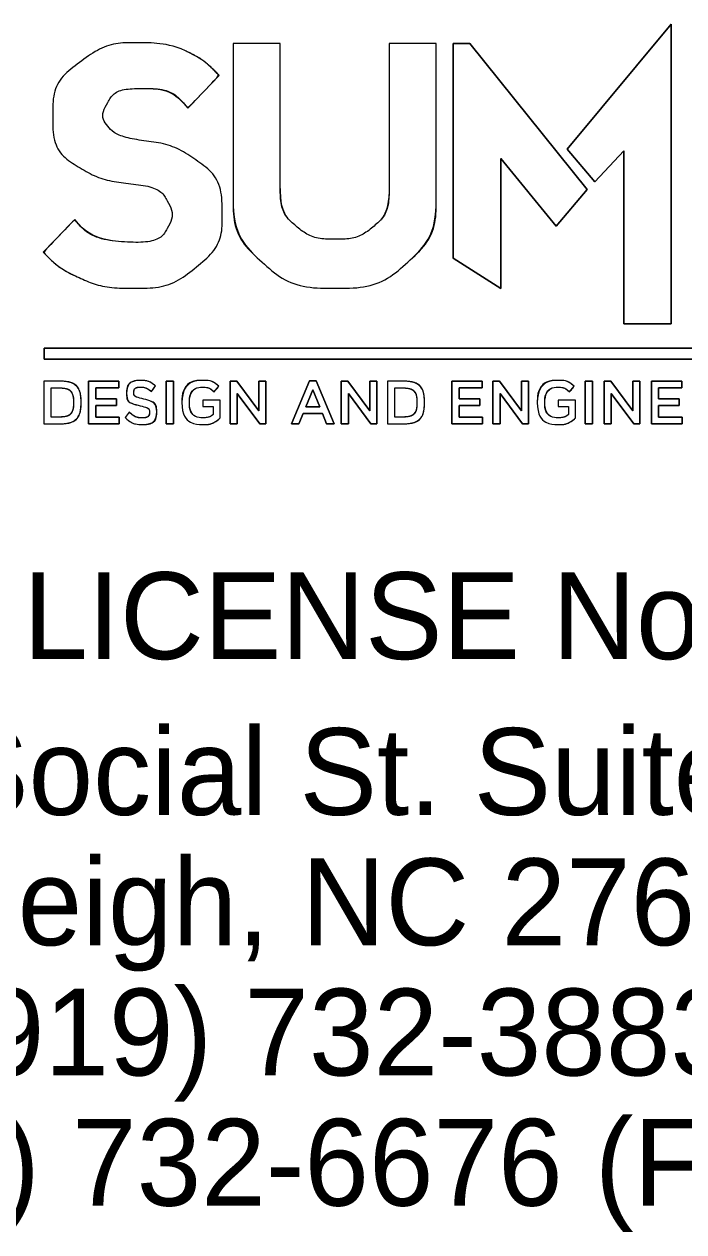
# Model space of a CAD drawing. Extents: x -0.67 to 3.05, y 0 to 1.8.
# Drawn here: x 2.6579 to 2.7165, y 1.2524 to 1.3595 of the extents above; entities that cross this region are included whole.
import ezdxf

# ---------------------------------------------------------------- set-up
doc = ezdxf.new("R2010")
doc.units = 0
doc.layers.add('Sheet Plan CELL', color=7, linetype='Continuous')

msp = doc.modelspace()

# ---------------------------------------------------------------- linework, layer by layer
at = {"layer": 'Sheet Plan CELL'}
for p, q in [((2.67246, 1.35204), (2.67524, 1.35495)), ((2.66243, 1.34217), (2.65964, 1.33926)), ((2.66925, 1.32691), (2.66959, 1.32741)), ((2.6748, 1.32688), (2.67521, 1.32738)), ((2.70633, 1.32688), (2.70674, 1.32738)), ((2.66703, 1.32679), (2.66703, 1.32678)), ((2.66767, 1.32684), (2.66767, 1.32685)), ((2.66232, 1.32594), (2.66232, 1.32593)), ((2.66299, 1.32594), (2.66299, 1.32595)), ((2.66727, 1.32507), (2.66689, 1.3246)), ((2.66906, 1.32507), (2.66906, 1.32506)), ((2.6697, 1.32512), (2.6697, 1.32513)), ((2.67194, 1.32594), (2.67194, 1.32593)), ((2.67261, 1.32594), (2.67261, 1.32595)), ((2.69279, 1.32594), (2.69279, 1.32593)), ((2.69346, 1.32594), (2.69346, 1.32595)), ((2.70347, 1.32594), (2.70347, 1.32593)), ((2.70414, 1.32594), (2.70414, 1.32595))]:
    msp.add_line(p, q, dxfattribs=at)
for points in [[(2.71534, 1.3595), (2.71534, 1.33291), (2.71115, 1.33291), (2.71115, 1.34825), (2.70856, 1.3455), (2.70612, 1.34841), (2.71534, 1.3595)], [(2.70612, 1.34841), (2.70856, 1.3455), (2.71115, 1.34825), (2.71115, 1.33291), (2.71534, 1.33291), (2.71534, 1.3595), (2.70612, 1.34841)], [(2.68066, 1.34522), (2.68066, 1.35777), (2.67647, 1.35777), (2.67647, 1.34406)], [(2.69451, 1.34406), (2.69451, 1.35777), (2.69032, 1.35777), (2.69032, 1.34522)], [(2.69749, 1.35777), (2.70788, 1.34484), (2.70514, 1.34158), (2.70023, 1.34757), (2.70023, 1.33606), (2.69601, 1.33874), (2.69601, 1.35777), (2.69749, 1.35777)], [(2.69601, 1.35777), (2.69601, 1.33874), (2.70023, 1.33606), (2.70023, 1.34757), (2.70514, 1.34158), (2.70788, 1.34484), (2.69749, 1.35777), (2.69601, 1.35777)], [(2.76119, 1.32977), (2.65972, 1.32977), (2.65972, 1.33077), (2.76119, 1.33077), (2.76119, 1.32977)], [(2.76119, 1.33077), (2.65972, 1.33077), (2.65972, 1.32977), (2.76119, 1.32977), (2.76119, 1.33077)], [(2.66106, 1.32783), (2.6597, 1.32783), (2.6597, 1.32405), (2.66106, 1.32405)], [(2.66106, 1.32465), (2.66034, 1.32465), (2.66034, 1.32723), (2.66106, 1.32723)], [(2.66365, 1.32783), (2.66635, 1.32783), (2.66635, 1.32724), (2.66429, 1.32724), (2.66429, 1.32625), (2.66612, 1.32625), (2.66612, 1.32566), (2.66429, 1.32566), (2.66429, 1.32464), (2.66637, 1.32464), (2.66637, 1.32405), (2.66365, 1.32405), (2.66365, 1.32783)], [(2.66365, 1.32405), (2.66637, 1.32405), (2.66637, 1.32464), (2.66429, 1.32464), (2.66429, 1.32566), (2.66612, 1.32566), (2.66612, 1.32625), (2.66429, 1.32625), (2.66429, 1.32724), (2.66635, 1.32724), (2.66635, 1.32783), (2.66365, 1.32783), (2.66365, 1.32405)], [(2.67054, 1.32783), (2.67118, 1.32783), (2.67118, 1.32405), (2.67054, 1.32405), (2.67054, 1.32783)], [(2.67054, 1.32405), (2.67118, 1.32405), (2.67118, 1.32783), (2.67054, 1.32783), (2.67054, 1.32405)], [(2.67622, 1.32783), (2.67681, 1.32783), (2.67876, 1.32521), (2.67876, 1.32783), (2.67938, 1.32783), (2.67938, 1.32405), (2.67885, 1.32405), (2.67685, 1.32674), (2.67685, 1.32405), (2.67622, 1.32405), (2.67622, 1.32783)], [(2.67622, 1.32405), (2.67685, 1.32405), (2.67685, 1.32674), (2.67885, 1.32405), (2.67938, 1.32405), (2.67938, 1.32783), (2.67876, 1.32783), (2.67876, 1.32521), (2.67681, 1.32783), (2.67622, 1.32783), (2.67622, 1.32405)], [(2.68326, 1.32786), (2.68386, 1.32786), (2.68546, 1.32405), (2.68478, 1.32405), (2.68441, 1.32496), (2.68269, 1.32496), (2.68232, 1.32405), (2.68167, 1.32405), (2.68326, 1.32786)], [(2.68167, 1.32405), (2.68232, 1.32405), (2.68269, 1.32496), (2.68441, 1.32496), (2.68478, 1.32405), (2.68546, 1.32405), (2.68386, 1.32786), (2.68326, 1.32786), (2.68167, 1.32405)], [(2.68608, 1.32783), (2.68667, 1.32783), (2.68861, 1.32521), (2.68861, 1.32783), (2.68924, 1.32783), (2.68924, 1.32405), (2.68871, 1.32405), (2.68671, 1.32674), (2.68671, 1.32405), (2.68608, 1.32405), (2.68608, 1.32783)], [(2.68608, 1.32405), (2.68671, 1.32405), (2.68671, 1.32674), (2.68871, 1.32405), (2.68924, 1.32405), (2.68924, 1.32783), (2.68861, 1.32783), (2.68861, 1.32521), (2.68667, 1.32783), (2.68608, 1.32783), (2.68608, 1.32405)], [(2.69153, 1.32783), (2.69018, 1.32783), (2.69018, 1.32405), (2.69153, 1.32405)], [(2.69153, 1.32465), (2.69082, 1.32465), (2.69082, 1.32723), (2.69153, 1.32723)], [(2.6959, 1.32783), (2.69859, 1.32783), (2.69859, 1.32724), (2.69653, 1.32724), (2.69653, 1.32625), (2.69836, 1.32625), (2.69836, 1.32566), (2.69653, 1.32566), (2.69653, 1.32464), (2.69861, 1.32464), (2.69861, 1.32405), (2.6959, 1.32405), (2.6959, 1.32783)], [(2.6959, 1.32405), (2.69861, 1.32405), (2.69861, 1.32464), (2.69653, 1.32464), (2.69653, 1.32566), (2.69836, 1.32566), (2.69836, 1.32625), (2.69653, 1.32625), (2.69653, 1.32724), (2.69859, 1.32724), (2.69859, 1.32783), (2.6959, 1.32783), (2.6959, 1.32405)], [(2.69953, 1.32783), (2.70012, 1.32783), (2.70207, 1.32521), (2.70207, 1.32783), (2.70269, 1.32783), (2.70269, 1.32405), (2.70216, 1.32405), (2.70016, 1.32674), (2.70016, 1.32405), (2.69953, 1.32405), (2.69953, 1.32783)], [(2.69953, 1.32405), (2.70016, 1.32405), (2.70016, 1.32674), (2.70216, 1.32405), (2.70269, 1.32405), (2.70269, 1.32783), (2.70207, 1.32783), (2.70207, 1.32521), (2.70012, 1.32783), (2.69953, 1.32783), (2.69953, 1.32405)], [(2.70773, 1.32783), (2.70837, 1.32783), (2.70837, 1.32405), (2.70773, 1.32405), (2.70773, 1.32783)], [(2.70773, 1.32405), (2.70837, 1.32405), (2.70837, 1.32783), (2.70773, 1.32783), (2.70773, 1.32405)], [(2.70939, 1.32783), (2.70998, 1.32783), (2.71193, 1.32521), (2.71193, 1.32783), (2.71256, 1.32783), (2.71256, 1.32405), (2.71202, 1.32405), (2.71002, 1.32674), (2.71002, 1.32405), (2.70939, 1.32405), (2.70939, 1.32783)], [(2.70939, 1.32405), (2.71002, 1.32405), (2.71002, 1.32674), (2.71202, 1.32405), (2.71256, 1.32405), (2.71256, 1.32783), (2.71193, 1.32783), (2.71193, 1.32521), (2.70998, 1.32783), (2.70939, 1.32783), (2.70939, 1.32405)], [(2.7136, 1.32783), (2.71629, 1.32783), (2.71629, 1.32724), (2.71423, 1.32724), (2.71423, 1.32625), (2.71606, 1.32625), (2.71606, 1.32566), (2.71423, 1.32566), (2.71423, 1.32464), (2.71632, 1.32464), (2.71632, 1.32405), (2.7136, 1.32405), (2.7136, 1.32783)], [(2.7136, 1.32405), (2.71632, 1.32405), (2.71632, 1.32464), (2.71423, 1.32464), (2.71423, 1.32566), (2.71606, 1.32566), (2.71606, 1.32625), (2.71423, 1.32625), (2.71423, 1.32724), (2.71629, 1.32724), (2.71629, 1.32783), (2.7136, 1.32783), (2.7136, 1.32405)], [(2.67534, 1.32457), (2.67534, 1.32616), (2.67379, 1.32616), (2.67379, 1.32558), (2.67472, 1.32558), (2.67472, 1.32487)], [(2.68418, 1.32555), (2.68355, 1.32706), (2.68293, 1.32555), (2.68418, 1.32555)], [(2.68293, 1.32555), (2.68355, 1.32706), (2.68418, 1.32555), (2.68293, 1.32555)], [(2.70687, 1.32457), (2.70687, 1.32616), (2.70532, 1.32616), (2.70532, 1.32558), (2.70625, 1.32558), (2.70625, 1.32487)]]:
    msp.add_lwpolyline(points, dxfattribs=at)
for points, degree in [([(2.67225, 1.35713), (2.67331, 1.35664), (2.67431, 1.35592), (2.67524, 1.35495), (2.67524, 1.35495), (2.67246, 1.35204), (2.67246, 1.35204), (2.67153, 1.35321), (2.67023, 1.35379), (2.66855, 1.35379), (2.66688, 1.35379), (2.66582, 1.35338), (2.66535, 1.35255), (2.66489, 1.35173), (2.66489, 1.35103), (2.66535, 1.35045), (2.66582, 1.34987), (2.66688, 1.34943), (2.66855, 1.34914), (2.67032, 1.34895), (2.67192, 1.34834), (2.67336, 1.34732), (2.6748, 1.34631), (2.67552, 1.34469), (2.67552, 1.34246), (2.67552, 1.34071), (2.67475, 1.33921), (2.67322, 1.33796), (2.67168, 1.3367), (2.66989, 1.33607), (2.66784, 1.33607), (2.6659, 1.33607), (2.66428, 1.33636), (2.66298, 1.33694), (2.66168, 1.33752), (2.66057, 1.33829), (2.65964, 1.33926), (2.65964, 1.33926), (2.66243, 1.34217), (2.66243, 1.34217), (2.66335, 1.34101), (2.66493, 1.34033), (2.66716, 1.34013), (2.66902, 1.34013), (2.67018, 1.34055), (2.67064, 1.34137), (2.6711, 1.34219), (2.6711, 1.34301), (2.67064, 1.34384), (2.67018, 1.34466), (2.66902, 1.34517), (2.66716, 1.34536), (2.66549, 1.34556), (2.66396, 1.34609), (2.66256, 1.34696), (2.66117, 1.34783), (2.66047, 1.34933), (2.66047, 1.35146), (2.66047, 1.35339), (2.66127, 1.35494), (2.66285, 1.3561), (2.66443, 1.35727), (2.66606, 1.35785), (2.66773, 1.35785), (2.66967, 1.35785), (2.67118, 1.35761), (2.67225, 1.35713)], 3), ([(2.67225, 1.35713), (2.67118, 1.35761), (2.66967, 1.35785), (2.66773, 1.35785), (2.66606, 1.35785), (2.66443, 1.35727), (2.66285, 1.3561), (2.66127, 1.35494), (2.66047, 1.35339), (2.66047, 1.35146), (2.66047, 1.34933), (2.66117, 1.34783), (2.66256, 1.34696), (2.66396, 1.34609), (2.66549, 1.34556), (2.66716, 1.34536), (2.66902, 1.34517), (2.67018, 1.34466), (2.67064, 1.34384), (2.6711, 1.34301), (2.6711, 1.34219), (2.67064, 1.34137), (2.67018, 1.34055), (2.66902, 1.34013), (2.66716, 1.34013), (2.66493, 1.34033), (2.66335, 1.34101), (2.66243, 1.34217)], 3), ([(2.68066, 1.35777), (2.68066, 1.35777), (2.68066, 1.34522), (2.68066, 1.34522), (2.68066, 1.34357), (2.68113, 1.34236), (2.68206, 1.34159), (2.68299, 1.34081), (2.68416, 1.34042), (2.68555, 1.34042), (2.68694, 1.34042), (2.68805, 1.34081), (2.68898, 1.34159), (2.68991, 1.34236), (2.69032, 1.34357), (2.69032, 1.34522), (2.69032, 1.34522), (2.69032, 1.35777), (2.69032, 1.35777), (2.69032, 1.35777), (2.69451, 1.35777), (2.69451, 1.35777), (2.69451, 1.35777), (2.69451, 1.34406), (2.69451, 1.34406), (2.69451, 1.34183), (2.6937, 1.33994), (2.69198, 1.33839), (2.69026, 1.33684), (2.68813, 1.33607), (2.68553, 1.33607), (2.68293, 1.33607), (2.68077, 1.33684), (2.67905, 1.33839), (2.67733, 1.33994), (2.67647, 1.34183), (2.67647, 1.34406), (2.67647, 1.34406), (2.67647, 1.35777), (2.67647, 1.35777), (2.67647, 1.35777), (2.68066, 1.35777), (2.68066, 1.35777)], 3), ([(2.67524, 1.35495), (2.67431, 1.35592), (2.67331, 1.35664), (2.67225, 1.35713)], 2), ([(2.65964, 1.33926), (2.66057, 1.33829), (2.66168, 1.33752), (2.66298, 1.33694), (2.66428, 1.33636), (2.6659, 1.33607), (2.66784, 1.33607), (2.66989, 1.33607), (2.67168, 1.3367), (2.67322, 1.33796), (2.67475, 1.33921), (2.67552, 1.34071), (2.67552, 1.34246), (2.67552, 1.34469), (2.6748, 1.34631), (2.67336, 1.34732), (2.67192, 1.34834), (2.67032, 1.34895), (2.66855, 1.34914), (2.66688, 1.34943), (2.66582, 1.34987), (2.66535, 1.35045), (2.66489, 1.35103), (2.66489, 1.35173), (2.66535, 1.35255), (2.66582, 1.35338), (2.66688, 1.35379), (2.66855, 1.35379), (2.67023, 1.35379), (2.67153, 1.35321), (2.67246, 1.35204)], 3), ([(2.69032, 1.34522), (2.69032, 1.34357), (2.68991, 1.34236), (2.68898, 1.34159), (2.68805, 1.34081), (2.68694, 1.34042), (2.68555, 1.34042), (2.68416, 1.34042), (2.68299, 1.34081), (2.68206, 1.34159), (2.68113, 1.34236), (2.68066, 1.34357), (2.68066, 1.34522)], 3), ([(2.67647, 1.34406), (2.67647, 1.34183), (2.67733, 1.33994), (2.67905, 1.33839), (2.68077, 1.33684), (2.68293, 1.33607), (2.68553, 1.33607), (2.68813, 1.33607), (2.69026, 1.33684), (2.69198, 1.33839), (2.6937, 1.33994), (2.69451, 1.34183), (2.69451, 1.34406)], 3), ([(2.6597, 1.32783), (2.6597, 1.32783), (2.66106, 1.32783), (2.66106, 1.32783), (2.6622, 1.32783), (2.66299, 1.32702), (2.66299, 1.32595), (2.66299, 1.32595), (2.66299, 1.32594), (2.66299, 1.32594), (2.66299, 1.32487), (2.6622, 1.32405), (2.66106, 1.32405), (2.66106, 1.32405), (2.6597, 1.32405), (2.6597, 1.32405), (2.6597, 1.32405), (2.6597, 1.32783), (2.6597, 1.32783)], 3), ([(2.66034, 1.32723), (2.66034, 1.32723), (2.66034, 1.32465), (2.66034, 1.32465), (2.66034, 1.32465), (2.66106, 1.32465), (2.66106, 1.32465), (2.66182, 1.32465), (2.66232, 1.32519), (2.66232, 1.32593), (2.66232, 1.32593), (2.66232, 1.32594), (2.66232, 1.32594), (2.66232, 1.32668), (2.66182, 1.32723), (2.66106, 1.32723), (2.66106, 1.32723), (2.66034, 1.32723), (2.66034, 1.32723)], 3), ([(2.66299, 1.32595), (2.66299, 1.32702), (2.6622, 1.32783), (2.66106, 1.32783)], 2), ([(2.66106, 1.32723), (2.66182, 1.32723), (2.66232, 1.32668), (2.66232, 1.32594)], 2), ([(2.66689, 1.3246), (2.66689, 1.3246), (2.66727, 1.32507), (2.66727, 1.32507), (2.66762, 1.32476), (2.66797, 1.32458), (2.66842, 1.32458), (2.66881, 1.32458), (2.66906, 1.32478), (2.66906, 1.32506), (2.66906, 1.32506), (2.66906, 1.32507), (2.66906, 1.32507), (2.66906, 1.32534), (2.66892, 1.32548), (2.66824, 1.32565), (2.66747, 1.32584), (2.66703, 1.32608), (2.66703, 1.32678), (2.66703, 1.32678), (2.66703, 1.32679), (2.66703, 1.32679), (2.66703, 1.32744), (2.66755, 1.32789), (2.66827, 1.32789), (2.6688, 1.32789), (2.66922, 1.32772), (2.66959, 1.32741), (2.66959, 1.32741), (2.66925, 1.32691), (2.66925, 1.32691), (2.66892, 1.32716), (2.6686, 1.3273), (2.66826, 1.3273), (2.66789, 1.3273), (2.66767, 1.3271), (2.66767, 1.32685), (2.66767, 1.32685), (2.66767, 1.32684), (2.66767, 1.32684), (2.66767, 1.32655), (2.66784, 1.32642), (2.66854, 1.32624), (2.66931, 1.32605), (2.6697, 1.32576), (2.6697, 1.32513), (2.6697, 1.32513), (2.6697, 1.32512), (2.6697, 1.32512), (2.6697, 1.32441), (2.66917, 1.32399), (2.6684, 1.32399), (2.66785, 1.32399), (2.66732, 1.32419), (2.66689, 1.3246)], 3), ([(2.66959, 1.32741), (2.66922, 1.32772), (2.6688, 1.32789), (2.66827, 1.32789), (2.66755, 1.32789), (2.66703, 1.32744), (2.66703, 1.32679)], 3), ([(2.66767, 1.32685), (2.66767, 1.3271), (2.66789, 1.3273), (2.66826, 1.3273), (2.6686, 1.3273), (2.66892, 1.32716), (2.66925, 1.32691)], 3), ([(2.67194, 1.32593), (2.67194, 1.32593), (2.67194, 1.32594), (2.67194, 1.32594), (2.67194, 1.327), (2.67271, 1.3279), (2.67381, 1.3279), (2.67444, 1.3279), (2.67483, 1.32771), (2.67521, 1.32738), (2.67521, 1.32738), (2.6748, 1.32688), (2.6748, 1.32688), (2.67452, 1.32713), (2.67425, 1.32729), (2.67378, 1.32729), (2.67311, 1.32729), (2.67261, 1.32668), (2.67261, 1.32595), (2.67261, 1.32595), (2.67261, 1.32594), (2.67261, 1.32594), (2.67261, 1.32516), (2.6731, 1.32459), (2.67384, 1.32459), (2.67418, 1.32459), (2.6745, 1.3247), (2.67472, 1.32487), (2.67472, 1.32487), (2.67472, 1.32558), (2.67472, 1.32558), (2.67472, 1.32558), (2.67379, 1.32558), (2.67379, 1.32558), (2.67379, 1.32558), (2.67379, 1.32616), (2.67379, 1.32616), (2.67379, 1.32616), (2.67534, 1.32616), (2.67534, 1.32616), (2.67534, 1.32616), (2.67534, 1.32457), (2.67534, 1.32457), (2.67498, 1.32425), (2.67446, 1.32398), (2.67382, 1.32398), (2.67268, 1.32398), (2.67194, 1.32482), (2.67194, 1.32593)], 3), ([(2.67521, 1.32738), (2.67483, 1.32771), (2.67444, 1.3279), (2.67381, 1.3279), (2.67271, 1.3279), (2.67194, 1.327), (2.67194, 1.32594)], 3), ([(2.67261, 1.32595), (2.67261, 1.32668), (2.67311, 1.32729), (2.67378, 1.32729), (2.67425, 1.32729), (2.67452, 1.32713), (2.6748, 1.32688)], 3), ([(2.69018, 1.32783), (2.69018, 1.32783), (2.69153, 1.32783), (2.69153, 1.32783), (2.69267, 1.32783), (2.69346, 1.32702), (2.69346, 1.32595), (2.69346, 1.32595), (2.69346, 1.32594), (2.69346, 1.32594), (2.69346, 1.32487), (2.69267, 1.32405), (2.69153, 1.32405), (2.69153, 1.32405), (2.69018, 1.32405), (2.69018, 1.32405), (2.69018, 1.32405), (2.69018, 1.32783), (2.69018, 1.32783)], 3), ([(2.69082, 1.32723), (2.69082, 1.32723), (2.69082, 1.32465), (2.69082, 1.32465), (2.69082, 1.32465), (2.69153, 1.32465), (2.69153, 1.32465), (2.69229, 1.32465), (2.69279, 1.32519), (2.69279, 1.32593), (2.69279, 1.32593), (2.69279, 1.32594), (2.69279, 1.32594), (2.69279, 1.32668), (2.69229, 1.32723), (2.69153, 1.32723), (2.69153, 1.32723), (2.69082, 1.32723), (2.69082, 1.32723)], 3), ([(2.69346, 1.32595), (2.69346, 1.32702), (2.69267, 1.32783), (2.69153, 1.32783)], 2), ([(2.69153, 1.32723), (2.69229, 1.32723), (2.69279, 1.32668), (2.69279, 1.32594)], 2), ([(2.70347, 1.32593), (2.70347, 1.32593), (2.70347, 1.32594), (2.70347, 1.32594), (2.70347, 1.327), (2.70424, 1.3279), (2.70534, 1.3279), (2.70597, 1.3279), (2.70636, 1.32771), (2.70674, 1.32738), (2.70674, 1.32738), (2.70633, 1.32688), (2.70633, 1.32688), (2.70605, 1.32713), (2.70578, 1.32729), (2.70531, 1.32729), (2.70464, 1.32729), (2.70414, 1.32668), (2.70414, 1.32595), (2.70414, 1.32595), (2.70414, 1.32594), (2.70414, 1.32594), (2.70414, 1.32516), (2.70463, 1.32459), (2.70537, 1.32459), (2.70571, 1.32459), (2.70602, 1.3247), (2.70625, 1.32487), (2.70625, 1.32487), (2.70625, 1.32558), (2.70625, 1.32558), (2.70625, 1.32558), (2.70532, 1.32558), (2.70532, 1.32558), (2.70532, 1.32558), (2.70532, 1.32616), (2.70532, 1.32616), (2.70532, 1.32616), (2.70687, 1.32616), (2.70687, 1.32616), (2.70687, 1.32616), (2.70687, 1.32457), (2.70687, 1.32457), (2.70651, 1.32425), (2.70599, 1.32398), (2.70535, 1.32398), (2.70421, 1.32398), (2.70347, 1.32482), (2.70347, 1.32593)], 3), ([(2.70674, 1.32738), (2.70636, 1.32771), (2.70597, 1.3279), (2.70534, 1.3279), (2.70424, 1.3279), (2.70347, 1.327), (2.70347, 1.32594)], 3), ([(2.70414, 1.32595), (2.70414, 1.32668), (2.70464, 1.32729), (2.70531, 1.32729), (2.70578, 1.32729), (2.70605, 1.32713), (2.70633, 1.32688)], 3), ([(2.66703, 1.32678), (2.66703, 1.32608), (2.66747, 1.32584), (2.66824, 1.32565), (2.66892, 1.32548), (2.66906, 1.32534), (2.66906, 1.32507)], 3), ([(2.6697, 1.32513), (2.6697, 1.32576), (2.66931, 1.32605), (2.66854, 1.32624), (2.66784, 1.32642), (2.66767, 1.32655), (2.66767, 1.32684)], 3), ([(2.66106, 1.32405), (2.6622, 1.32405), (2.66299, 1.32487), (2.66299, 1.32594)], 2), ([(2.66232, 1.32593), (2.66232, 1.32519), (2.66182, 1.32465), (2.66106, 1.32465)], 2), ([(2.66689, 1.3246), (2.66732, 1.32419), (2.66785, 1.32399), (2.6684, 1.32399), (2.66917, 1.32399), (2.6697, 1.32441), (2.6697, 1.32512)], 3), ([(2.66906, 1.32506), (2.66906, 1.32478), (2.66881, 1.32458), (2.66842, 1.32458), (2.66797, 1.32458), (2.66762, 1.32476), (2.66727, 1.32507)], 3), ([(2.67194, 1.32593), (2.67194, 1.32482), (2.67268, 1.32398), (2.67382, 1.32398), (2.67446, 1.32398), (2.67498, 1.32425), (2.67534, 1.32457)], 3), ([(2.67472, 1.32487), (2.6745, 1.3247), (2.67418, 1.32459), (2.67384, 1.32459), (2.6731, 1.32459), (2.67261, 1.32516), (2.67261, 1.32594)], 3), ([(2.69153, 1.32405), (2.69267, 1.32405), (2.69346, 1.32487), (2.69346, 1.32594)], 2), ([(2.69279, 1.32593), (2.69279, 1.32519), (2.69229, 1.32465), (2.69153, 1.32465)], 2), ([(2.70347, 1.32593), (2.70347, 1.32482), (2.70421, 1.32398), (2.70535, 1.32398), (2.70599, 1.32398), (2.70651, 1.32425), (2.70687, 1.32457)], 3), ([(2.70625, 1.32487), (2.70602, 1.3247), (2.70571, 1.32459), (2.70537, 1.32459), (2.70463, 1.32459), (2.70414, 1.32516), (2.70414, 1.32594)], 3)]:
    msp.add_open_spline(points, degree=degree, dxfattribs=at)

# ---------------------------------------------------------------- texts
for s, p in [('NC FIRM LICENSE No: C-5176', (2.61209, 1.30318)), ('1000 Social St. Suite 800.', (2.62569, 1.28936)), ('Raleigh, NC 27609', (2.64191, 1.2778)), ('(919) 732-3883', (2.65058, 1.26625)), ('(919) 732-6676 (FAX)', (2.63529, 1.2547))]:
    msp.add_text(s, height=0.0077015, rotation=360, dxfattribs=at).set_placement(p)

doc.saveas('drawing.dxf')
